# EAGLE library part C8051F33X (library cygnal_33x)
Cygnal C8051F330/1 microcontroller
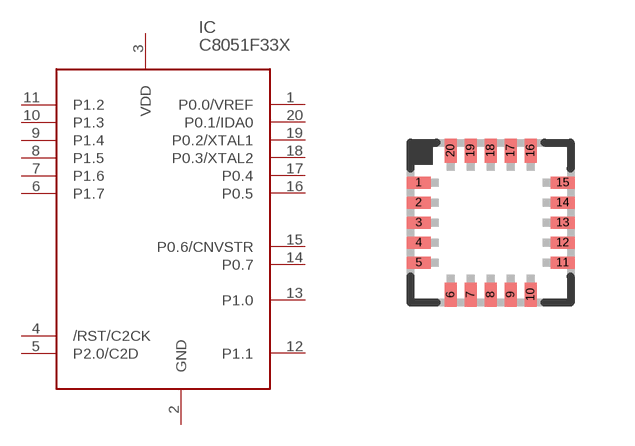
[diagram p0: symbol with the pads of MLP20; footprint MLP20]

Designator prefix IC

## C8051F33X  [MLP20]
1  P0.0/VREF  pas
2  GND  pwr
3  VDD  pwr
4  /RST/C2CK  pas
5  P2.0/C2D  pas
6  P1.7  pas
7  P1.6  pas
8  P1.5  pas
9  P1.4  pas
10  P1.3  pas
11  P1.2  pas
12  P1.1  pas
13  P1.0  pas
14  P0.7  pas
15  P0.6/CNVSTR  pas
16  P0.5  pas
17  P0.4  pas
18  P0.3/XTAL2  pas
19  P0.2/XTAL1  pas
20  P0.1/IDA0  pas

## Footprint MLP20 (pad centres in mm)
Cygnal MLP20
smd 0.6 x 0.3: 1 -1.8,1; 2 -1.8,0.5; 3 -1.8,0; 4 -1.8,-0.5; 5 -1.8,-1; 11 1.8,-1; 12 1.8,-0.5; 13 1.8,0; 14 1.8,0.5; 15 1.8,1
smd 0.3 x 0.6: 6 -1,-1.8; 7 -0.5,-1.8; 8 0,-1.8; 9 0.5,-1.8; 10 1,-1.8; 16 1,1.8; 17 0.5,1.8; 18 0,1.8; 19 -0.5,1.8; 20 -1,1.8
